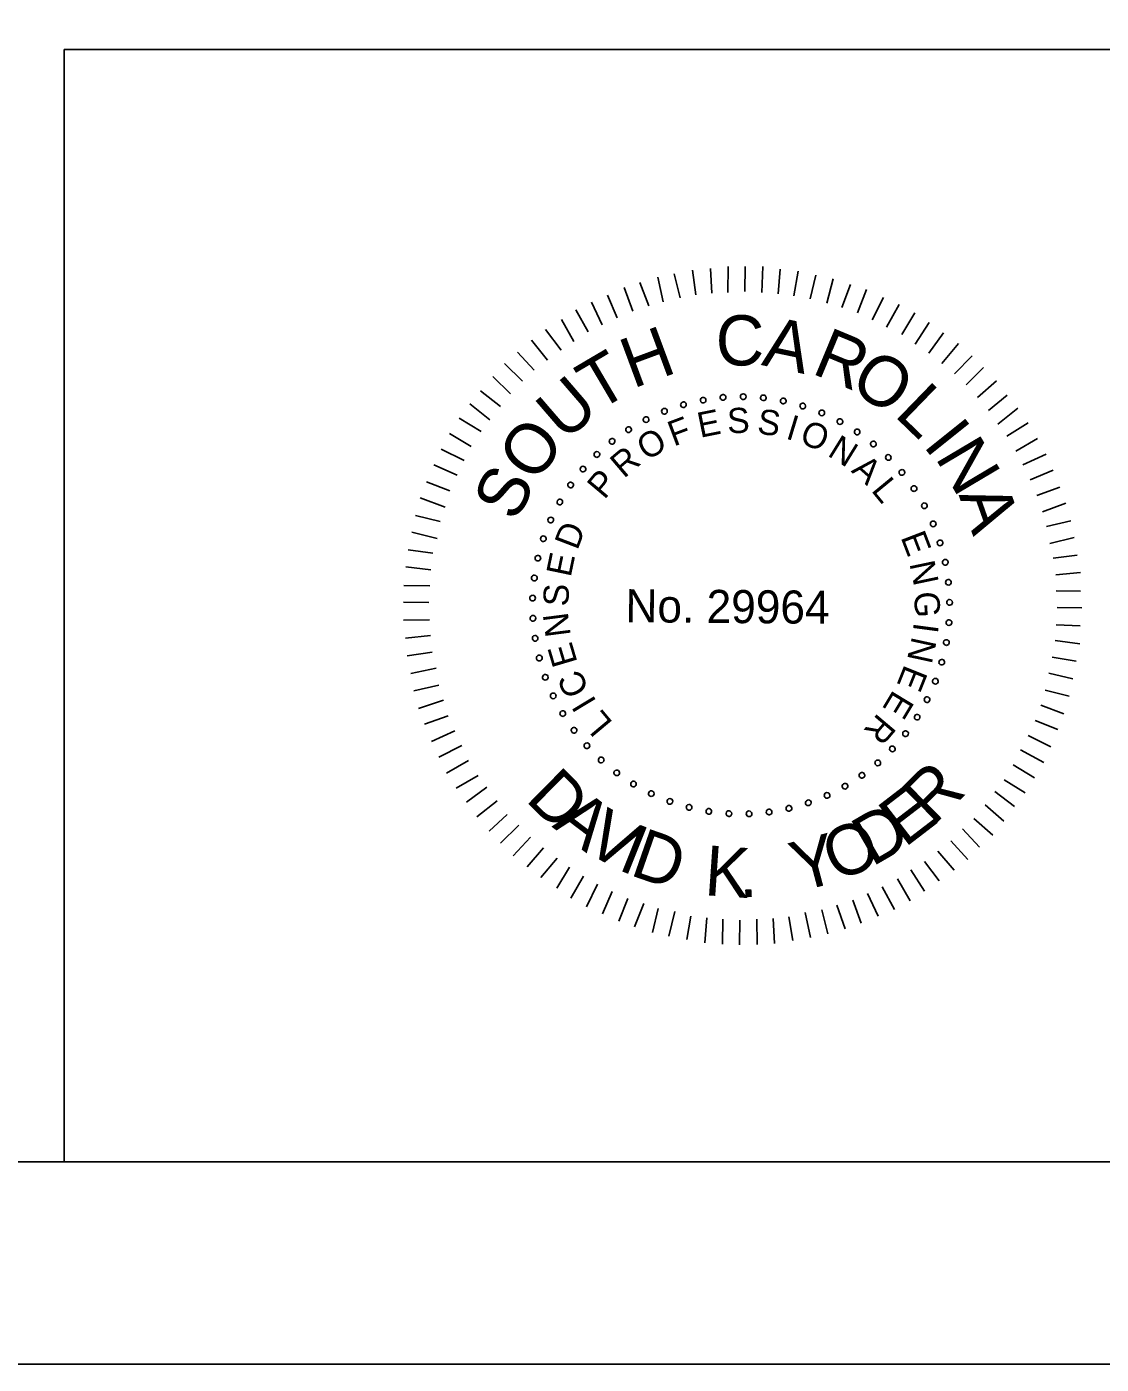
# Model space of a CAD drawing. Extents: x -121.2 to -24.9, y 6.4 to 65.9.
# Drawn here: x -61.05 to -53.97, y 6.35 to 15.17 of the extents above; entities that cross this region are included whole.
import ezdxf

# ---------------------------------------------------------------- set-up
doc = ezdxf.new("R2010")
doc.units = 0
for name, color, linetype in [('BR_BORDER LINES', 7, 'Continuous'), ('BR_TEXT', 7, 'Continuous'), ('Level 31', 7, 'Continuous')]:
    doc.layers.add(name, color=color, linetype=linetype)

msp = doc.modelspace()

# ---------------------------------------------------------------- linework, layer by layer
at = {"layer": 'BR_BORDER LINES'}
for p, q in [((-60.8035, 15.017), (-46.4963, 15.017)), ((-60.8035, 7.6835), (-60.8035, 15.017)), ((-116.2718, 7.6833), (-26.4955, 7.6833))]:
    msp.add_line(p, q, dxfattribs=at)
at = {"layer": 'BR_TEXT'}
for p, q in [((-56.4283, 13.4151), (-56.4269, 13.5867)), ((-56.3162, 13.4209), (-56.3148, 13.5857)), ((-56.204, 13.4132), (-56.198, 13.5848)), ((-56.8545, 13.3522), (-56.8897, 13.5149)), ((-56.7444, 13.3787), (-56.7821, 13.537)), ((-56.639, 13.3985), (-56.6628, 13.5611)), ((-56.5336, 13.4091), (-56.5438, 13.5716)), ((-56.0966, 13.4055), (-56.0838, 13.5678)), ((-55.9937, 13.3931), (-55.9648, 13.5553)), ((-55.8863, 13.3716), (-55.8484, 13.5292)), ((-55.7767, 13.3433), (-55.7341, 13.5054)), ((-57.0564, 13.292), (-57.1123, 13.4481)), ((-56.9508, 13.3256), (-57.0091, 13.4793)), ((-55.6786, 13.315), (-55.62, 13.4678)), ((-55.5735, 13.2798), (-55.515, 13.4349)), ((-57.2585, 13.2021), (-57.3283, 13.3515)), ((-57.1597, 13.2471), (-57.2226, 13.3964)), ((-55.4778, 13.2332), (-55.4034, 13.3814)), ((-55.3821, 13.1866), (-55.2985, 13.3347)), ((-57.4448, 13.0916), (-57.5259, 13.2365)), ((-57.3504, 13.1548), (-57.4316, 13.2997)), ((-55.2817, 13.1378), (-55.1959, 13.2812)), ((-57.5276, 13.0351), (-57.6318, 13.1709)), ((-55.193, 13.073), (-55.1026, 13.2165)), ((-55.1043, 13.015), (-55.007, 13.1493)), ((-57.6174, 12.9672), (-57.7239, 13.1008)), ((-55.0179, 12.9457), (-54.9093, 13.0776)), ((-57.705, 12.9015), (-57.8161, 13.0214)), ((-54.9338, 12.8786), (-54.8184, 12.9966)), ((-57.7834, 12.829), (-57.9014, 12.9466)), ((-54.8589, 12.8048), (-54.7435, 12.9205)), ((-57.8618, 12.7471), (-57.9777, 12.8603)), ((-54.784, 12.7217), (-54.6572, 12.8329)), ((-57.9289, 12.663), (-58.0608, 12.7671)), ((-54.7115, 12.6365), (-54.5871, 12.7384)), ((-57.9983, 12.5744), (-58.1301, 12.6808)), ((-54.6481, 12.5467), (-54.5168, 12.6509)), ((-58.0562, 12.4971), (-58.1996, 12.5852)), ((-54.5894, 12.4684), (-54.4491, 12.5542)), ((-58.1211, 12.3992), (-58.2645, 12.485)), ((-54.5306, 12.3695), (-54.3881, 12.453)), ((-58.1676, 12.308), (-58.318, 12.3824)), ((-54.4833, 12.2776), (-54.3294, 12.3495)), ((-58.2142, 12.21), (-58.3669, 12.2777)), ((-58.2608, 12.1074), (-58.4159, 12.1659)), ((-54.4361, 12.1788), (-54.2845, 12.2439)), ((-54.3912, 12.0754), (-54.2396, 12.1314)), ((-58.2937, 12.0001), (-58.4579, 12.0609)), ((-54.3555, 11.9676), (-54.2016, 12.0258)), ((-58.3265, 11.9043), (-58.4887, 11.9445)), ((-54.3287, 11.8713), (-54.1683, 11.9088)), ((-58.3458, 11.7923), (-58.5124, 11.8348)), ((-54.3068, 11.7589), (-54.1463, 11.7988)), ((-58.374, 11.6964), (-58.5363, 11.7184)), ((-54.2847, 11.6626), (-54.1267, 11.6819)), ((-58.3864, 11.5867), (-58.5509, 11.6063)), ((-54.2674, 11.5527), (-54.1047, 11.5696)), ((-58.3941, 11.4814), (-58.5657, 11.4829)), ((-58.3996, 11.3717), (-58.5666, 11.3731)), ((-54.2636, 11.4473), (-54.1034, 11.446)), ((-54.2577, 11.3375), (-54.0952, 11.3362)), ((-58.396, 11.2572), (-58.5676, 11.254)), ((-54.2655, 11.2231), (-54.1053, 11.2172)), ((-58.3899, 11.1541), (-58.5548, 11.135)), ((-54.2709, 11.1201), (-54.1086, 11.0983)), ((-58.3794, 11.0443), (-58.5421, 11.0204)), ((-58.3528, 10.9388), (-58.5201, 10.9035)), ((-54.2901, 11.0105), (-54.1325, 10.984)), ((-54.3139, 10.9054), (-54.1539, 10.8675)), ((-58.3354, 10.8264), (-58.4983, 10.7889)), ((-54.3376, 10.7934), (-54.1778, 10.7532)), ((-58.3042, 10.7279), (-58.4694, 10.672)), ((-54.366, 10.6953), (-54.2131, 10.6368)), ((-58.2731, 10.6246), (-58.4291, 10.5686)), ((-54.4034, 10.5926), (-54.2528, 10.5341)), ((-58.2281, 10.5258), (-58.3819, 10.4539)), ((-54.45, 10.4946), (-54.2995, 10.4202)), ((-58.1831, 10.4293), (-58.3347, 10.3505)), ((-58.1382, 10.3305), (-58.2829, 10.247)), ((-54.4989, 10.3989), (-54.3462, 10.3175)), ((-58.0749, 10.2316), (-58.2197, 10.1481)), ((-54.5477, 10.3009), (-54.4065, 10.215)), ((-58.0183, 10.1533), (-58.1518, 10.056)), ((-54.6081, 10.2029), (-54.4692, 10.1171)), ((-57.9504, 10.0635), (-58.084, 9.9593)), ((-54.6681, 10.1256), (-54.5385, 10.0262)), ((-57.8847, 9.9737), (-58.0024, 9.8648)), ((-54.733, 10.0369), (-54.6103, 9.9306)), ((-57.8075, 9.9044), (-57.9275, 9.7841)), ((-54.8831, 9.8802), (-54.7696, 9.758)), ((-54.8069, 9.9483), (-54.682, 9.8374)), ((-57.7304, 9.8237), (-57.8435, 9.7011)), ((-54.9592, 9.8008), (-54.8459, 9.6763)), ((-57.6439, 9.7544), (-57.7526, 9.6293)), ((-55.0444, 9.7329), (-54.938, 9.6061)), ((-57.5553, 9.6849), (-57.6616, 9.5577)), ((-57.4734, 9.627), (-57.5569, 9.4882)), ((-55.1319, 9.6649), (-55.0369, 9.536)), ((-57.38, 9.5668), (-57.4636, 9.4233)), ((-55.3114, 9.5497), (-55.2279, 9.4048)), ((-55.2216, 9.6084), (-55.1336, 9.4682)), ((-57.2889, 9.5134), (-57.3612, 9.3652)), ((-57.1909, 9.4668), (-57.2563, 9.3186)), ((-55.509, 9.4529), (-55.4371, 9.3036)), ((-55.4125, 9.4979), (-55.3314, 9.3485)), ((-57.0884, 9.4202), (-57.1468, 9.2696)), ((-56.9834, 9.3873), (-57.0442, 9.2322)), ((-56.8875, 9.3544), (-56.9254, 9.1969)), ((-55.8098, 9.3455), (-55.7698, 9.1873)), ((-55.7111, 9.3768), (-55.6551, 9.2207)), ((-55.6055, 9.408), (-55.5495, 9.2564)), ((-56.7778, 9.3353), (-56.8181, 9.1708)), ((-56.6728, 9.3046), (-56.6992, 9.1493)), ((-56.5676, 9.2924), (-56.5805, 9.1276)), ((-56.4624, 9.2846), (-56.4638, 9.1198)), ((-56.3504, 9.2768), (-56.3517, 9.1143)), ((-56.2381, 9.2828), (-56.2349, 9.1179)), ((-56.1306, 9.2887), (-56.1205, 9.1238)), ((-56.0275, 9.2993), (-56.0013, 9.1435)), ((-55.9197, 9.3282), (-55.8844, 9.1631))]:
    msp.add_line(p, q, dxfattribs=at)
for centre, start, end in [((-56.592, 12.7049), 10.60376, 190.60376), ((-56.592, 12.7049), 190.60376, 10.60376), ((-56.4604, 12.7227), 5.06529, 185.06529), ((-56.4604, 12.7227), 185.06529, 5.06529), ((-56.3276, 12.7278), 359.52683, 179.52683), ((-56.3276, 12.7278), 179.52683, 359.52683), ((-56.1949, 12.72), 173.98837, 353.98837), ((-56.1949, 12.72), 353.98837, 173.98837), ((-56.0636, 12.6995), 168.44991, 348.44991), ((-56.0636, 12.6995), 348.44991, 168.44991), ((-56.8472, 12.6316), 21.68068, 201.68068), ((-56.8472, 12.6316), 201.68068, 21.68068), ((-56.7214, 12.6744), 16.14222, 196.14222), ((-56.7214, 12.6744), 196.14222, 16.14222), ((-55.935, 12.6664), 162.91145, 342.91145), ((-55.935, 12.6664), 342.91145, 162.91145), ((-55.8101, 12.621), 157.37299, 337.37299), ((-55.8101, 12.621), 337.37299, 157.37299), ((-57.0835, 12.5106), 32.7576, 212.7576), ((-57.0835, 12.5106), 212.7576, 32.7576), ((-56.9683, 12.5768), 27.21914, 207.21914), ((-56.9683, 12.5768), 207.21914, 27.21914), ((-55.6901, 12.5637), 151.83453, 331.83453), ((-55.6901, 12.5637), 331.83453, 151.83453), ((-57.1918, 12.4336), 38.29606, 218.29606), ((-57.1918, 12.4336), 218.29606, 38.29606), ((-55.5763, 12.4952), 146.29606, 326.29606), ((-55.5763, 12.4952), 326.29606, 146.29606), ((-55.4696, 12.416), 320.7576, 140.7576), ((-57.2921, 12.3465), 43.83453, 223.83453), ((-57.2921, 12.3465), 223.83453, 43.83453), ((-55.4696, 12.416), 140.7576, 320.7576), ((-55.371, 12.3269), 315.21914, 135.21914), ((-57.3836, 12.2502), 49.37299, 229.37299), ((-57.3836, 12.2502), 229.37299, 49.37299), ((-55.371, 12.3269), 135.21914, 315.21914), ((-55.2815, 12.2286), 129.68068, 309.68068), ((-55.2815, 12.2286), 309.68068, 129.68068), ((-57.4654, 12.1454), 54.91145, 234.91145), ((-57.4654, 12.1454), 234.91145, 54.91145), ((-55.202, 12.1222), 124.14222, 304.14222), ((-55.202, 12.1222), 304.14222, 124.14222), ((-57.5366, 12.0333), 60.44991, 240.44991), ((-57.5366, 12.0333), 240.44991, 60.44991), ((-55.133, 12.0086), 118.60376, 298.60376), ((-55.133, 12.0086), 298.60376, 118.60376), ((-57.5968, 11.9148), 65.98837, 245.98837), ((-57.5968, 11.9148), 245.98837, 65.98837), ((-55.0753, 11.8889), 113.06529, 293.06529), ((-55.0753, 11.8889), 293.06529, 113.06529), ((-57.6451, 11.791), 71.52683, 251.52683), ((-57.6451, 11.791), 251.52683, 71.52683), ((-55.0295, 11.7642), 107.52683, 287.52683), ((-55.0295, 11.7642), 287.52683, 107.52683), ((-57.6814, 11.6631), 77.06529, 257.06529), ((-57.6814, 11.6631), 257.06529, 77.06529), ((-54.9959, 11.6356), 101.98837, 281.98837), ((-54.9959, 11.6356), 281.98837, 101.98837), ((-57.7051, 11.5324), 82.60376, 262.60376), ((-57.7051, 11.5324), 262.60376, 82.60376), ((-54.9749, 11.5044), 96.44991, 276.44991), ((-54.9749, 11.5044), 276.44991, 96.44991), ((-57.7161, 11.4), 88.14222, 268.14222), ((-57.7161, 11.4), 268.14222, 88.14222), ((-54.9666, 11.3718), 90.91145, 270.91145), ((-54.9666, 11.3718), 270.91145, 90.91145), ((-57.7142, 11.2671), 93.68068, 273.68068), ((-57.7142, 11.2671), 273.68068, 93.68068), ((-54.9712, 11.239), 85.37299, 265.37299), ((-54.9712, 11.239), 265.37299, 85.37299), ((-57.6995, 11.135), 99.21914, 279.21914), ((-57.6995, 11.135), 279.21914, 99.21914), ((-54.9885, 11.1073), 79.83453, 259.83453), ((-54.9885, 11.1073), 259.83453, 79.83453), ((-57.6722, 11.005), 104.7576, 284.7576), ((-57.6722, 11.005), 284.7576, 104.7576), ((-55.0185, 10.9778), 74.29606, 254.29606), ((-55.0185, 10.9778), 254.29606, 74.29606), ((-57.6324, 10.8782), 110.29606, 290.29606), ((-57.6324, 10.8782), 290.29606, 110.29606), ((-55.0609, 10.8519), 68.7576, 248.7576), ((-55.0609, 10.8519), 248.7576, 68.7576), ((-57.5806, 10.7558), 115.83453, 295.83453), ((-57.5806, 10.7558), 295.83453, 115.83453), ((-55.1152, 10.7306), 63.21914, 243.21914), ((-55.1152, 10.7306), 243.21914, 63.21914), ((-57.5172, 10.6391), 121.37299, 301.37299), ((-57.5172, 10.6391), 301.37299, 121.37299), ((-55.181, 10.6151), 57.68068, 237.68068), ((-55.181, 10.6151), 237.68068, 57.68068), ((-57.4429, 10.5289), 126.91145, 306.91145), ((-57.4429, 10.5289), 306.91145, 126.91145), ((-55.2576, 10.5065), 52.14222, 232.14222), ((-55.2576, 10.5065), 232.14222, 52.14222), ((-57.3582, 10.4265), 132.44991, 312.44991), ((-57.3582, 10.4265), 312.44991, 132.44991), ((-55.3443, 10.4059), 46.60376, 226.60376), ((-55.3443, 10.4059), 226.60376, 46.60376), ((-57.2641, 10.3327), 137.98837, 317.98837), ((-57.2641, 10.3327), 317.98837, 137.98837), ((-55.4403, 10.314), 41.06529, 221.06529), ((-55.4403, 10.314), 221.06529, 41.06529), ((-57.1613, 10.2484), 143.52683, 323.52683), ((-57.1613, 10.2484), 323.52683, 143.52683), ((-55.5448, 10.2319), 35.52683, 215.52683), ((-55.5448, 10.2319), 215.52683, 35.52683), ((-57.0509, 10.1745), 149.06529, 329.06529), ((-57.0509, 10.1745), 329.06529, 149.06529), ((-55.6567, 10.1602), 29.98837, 209.98837), ((-55.6567, 10.1602), 209.98837, 29.98837), ((-56.9339, 10.1115), 154.60376, 334.60376), ((-56.9339, 10.1115), 334.60376, 154.60376), ((-56.8114, 10.0602), 160.14222, 340.14222), ((-56.8114, 10.0602), 340.14222, 160.14222), ((-55.8985, 10.0508), 18.91145, 198.91145), ((-55.8985, 10.0508), 198.91145, 18.91145), ((-55.775, 10.0997), 24.44991, 204.44991), ((-55.775, 10.0997), 204.44991, 24.44991), ((-56.6844, 10.0209), 165.68068, 345.68068), ((-56.6844, 10.0209), 345.68068, 165.68068), ((-56.5543, 9.994), 171.21914, 351.21914), ((-56.5543, 9.994), 351.21914, 171.21914), ((-56.4222, 9.9798), 176.7576, 356.7576), ((-56.4222, 9.9798), 356.7576, 176.7576), ((-56.2893, 9.9785), 2.29606, 182.29606), ((-56.2893, 9.9785), 182.29606, 2.29606), ((-56.1569, 9.9899), 7.83453, 187.83453), ((-56.1569, 9.9899), 187.83453, 7.83453), ((-56.0263, 10.0141), 13.37299, 193.37299), ((-56.0263, 10.0141), 193.37299, 13.37299)]:
    msp.add_arc(centre, 0.0187, start, end, dxfattribs=at)
at = {"layer": 'Level 31'}
msp.add_lwpolyline([(-121.1606, 6.3502), (-25.1605, 6.3502), (-25.1605, 65.0169), (-121.1606, 65.0169)], close=True, dxfattribs=at)

# ---------------------------------------------------------------- texts
at = {"layer": 'BR_TEXT'}
for s, height, rotation, p in [('C', 0.3309, 359.54822, (-56.5102, 12.9347)), ('A', 0.3309, 348.19813, (-56.2131, 12.9368)), ('H', 0.3309, 20.36371, (-57.0553, 12.7792)), ('R', 0.3309, 337.43439, (-55.8844, 12.8838)), ('T', 0.3309, 30.49921, (-57.2897, 12.6258)), ('O', 0.3305, 326.58689, (-55.6384, 12.7858)), ('U', 0.3309, 40.80225, (-57.5061, 12.4265)), ('L', 0.3309, 315.94879, (-55.3383, 12.6051)), ('E', 0.166, 11.41035, (-56.6115, 12.456)), ('S', 0.166, 2.20798, (-56.4306, 12.4853)), ('S', 0.166, 352.66081, (-56.2406, 12.4847)), ('O', 0.3309, 52.0267, (-57.705, 12.1493)), ('F', 0.166, 20.61271, (-56.7853, 12.3982)), ('I', 0.166, 343.11363, (-56.0533, 12.4527)), ('O', 0.166, 338.43918, (-55.9641, 12.4257)), ('I', 0.3309, 308.66128, (-55.1479, 12.407)), ('O', 0.166, 30.84774, (-56.9649, 12.3021)), ('N', 0.166, 328.20415, (-55.7785, 12.3419)), ('N', 0.3308, 300.70365, (-55.0663, 12.3286)), ('R', 0.166, 40.39491, (-57.1146, 12.1851)), ('S', 0.3305, 63.25114, (-57.8259, 11.8943)), ('A', 0.166, 318.65698, (-55.6212, 12.2352)), ('P', 0.166, 49.94209, (-57.2429, 12.0448)), ('L', 0.166, 309.45461, (-55.4885, 12.109)), ('A', 0.3309, 289.47921, (-54.9084, 12.0805)), ('D', 0.166, 69.03644, (-57.4214, 11.7108)), ('E', 0.166, 291.049, (-55.2914, 11.8015)), ('E', 0.166, 78.23881, (-57.4656, 11.533)), ('N', 0.166, 281.84664, (-55.2323, 11.6281)), ('S', 0.166, 87.78598, (-57.4808, 11.3436)), ('No. 29964', 0.21799, 359.52683, (-57.1045, 11.2412)), ('G', 0.166, 272.29946, (-55.201, 11.4406)), ('N', 0.166, 97.33316, (-57.4644, 11.1542)), ('I', 0.166, 262.40836, (-55.2019, 11.2438)), ('E', 0.166, 106.53552, (-57.419, 10.9767)), ('N', 0.166, 257.73391, (-55.2141, 11.1515)), ('E', 0.166, 248.18673, (-55.2621, 10.9676)), ('C', 0.166, 116.42662, (-57.3393, 10.7967)), ('E', 0.166, 238.98437, (-55.3367, 10.8003)), ('I', 0.166, 121.10107, (-57.2912, 10.717)), ('L', 0.166, 129.95951, (-57.1828, 10.5779)), ('R', 0.166, 229.78201, (-55.4371, 10.647)), ('D', 0.3295, 315.40526, (-57.7707, 10.0696)), ('R', 0.3295, 44.59474, (-55.0751, 9.8948)), ('E', 0.3295, 37.53391, (-55.2634, 9.7511)), ('A', 0.3295, 322.83772, (-57.5931, 9.8946)), ('V', 0.3295, 330.51792, (-57.3874, 9.7394)), ('D', 0.3295, 30.10145, (-55.4791, 9.626)), ('I', 0.3295, 338.19813, (-57.1628, 9.6131)), ('D', 0.3295, 340.79949, (-57.0831, 9.5773)), ('O', 0.3295, 22.42125, (-55.7171, 9.5271)), ('Y', 0.3295, 14.86491, (-55.9621, 9.4618)), ('K', 0.3295, 356.09796, (-56.5891, 9.4424)), ('.', 0.3295, 3.15879, (-56.3528, 9.4256))]:
    msp.add_text(s, height=height, rotation=rotation, dxfattribs=at).set_placement(p)

doc.saveas('drawing.dxf')
